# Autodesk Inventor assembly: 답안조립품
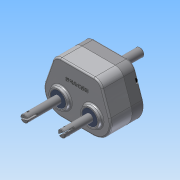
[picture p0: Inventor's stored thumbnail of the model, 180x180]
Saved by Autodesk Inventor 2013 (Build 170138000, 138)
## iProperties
Created: 2014-12
Part Number: 답안조립품
Document SubType Name: Assembly
Designer: Administrator
Author: Administrator
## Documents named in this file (14)
- C:\Users\Administrator\Desktop\441209V1016\441209V1016\답안조립품.iam
- C:\Users\Administrator\Desktop\441209V1016\441209V1016\본체.ipt
- C:\Users\Administrator\Desktop\441209V1016\441209V1016\M 5 x 35.ipt
- C:\Users\Administrator\Desktop\441209V1016\441209V1016\멈춤링.ipt
- C:\Users\Administrator\Desktop\441209V1016\441209V1016\메인기어.ipt
- C:\Users\Administrator\Desktop\441209V1016\441209V1016\메인축.ipt
- C:\Users\Administrator\Desktop\441209V1016\441209V1016\베어링- 6202.ipt
- C:\Users\Administrator\Desktop\441209V1016\441209V1016\베어링- 6203.ipt
- C:\Users\Administrator\Desktop\441209V1016\441209V1016\서브기어.ipt
- C:\Users\Administrator\Desktop\441209V1016\441209V1016\서브축.ipt
- C:\Users\Administrator\Desktop\441209V1016\441209V1016\오일시일-D-15.ipt
- C:\Users\Administrator\Desktop\441209V1016\441209V1016\오일시일-D-17.ipt
- C:\Users\Administrator\Desktop\441209V1016\441209V1016\커버.ipt
- C:\Users\Administrator\Desktop\441209V1016\441209V1016\키5x5.ipt
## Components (15 placed, 6 different names)
1. KS B 1003 - 미터 M 5 x 35:1
2. KS B 1336 17 x 1:1
3. KS B 2023 6202 - 15 x 35 x 11:1
4. KS B 2023 6203 - 17 x 40 x 12:1
5. KS B 2804 D D - 15 30 7:1 — 플러쉬:3
6. KS B 2804 D D - 17 30 8:1 — 플러쉬:1
7. KS B 1336 17 x 1:2
8. KS B 1336 17 x 1:3
9. KS B 2023 6202 - 15 x 35 x 11:2
10. KS B 2023 6203 - 17 x 40 x 12:2
11. KS B 2023 6203 - 17 x 40 x 12:3
12. KS B 2023 6203 - 17 x 40 x 12:4
13. KS B 2804 D D - 15 30 7:2 — 플러쉬:2
14. KS B 1003 - 미터 M 5 x 35:2
15. KS B 1003 - 미터 M 5 x 35:3
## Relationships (3: Flush 3)
- 플러쉬:1 [Flush]: KS B 2804 D D - 17 30 8:1
- 플러쉬:2 [Flush]: KS B 2804 D D - 15 30 7:2
- 플러쉬:3 [Flush]: KS B 2804 D D - 15 30 7:1
